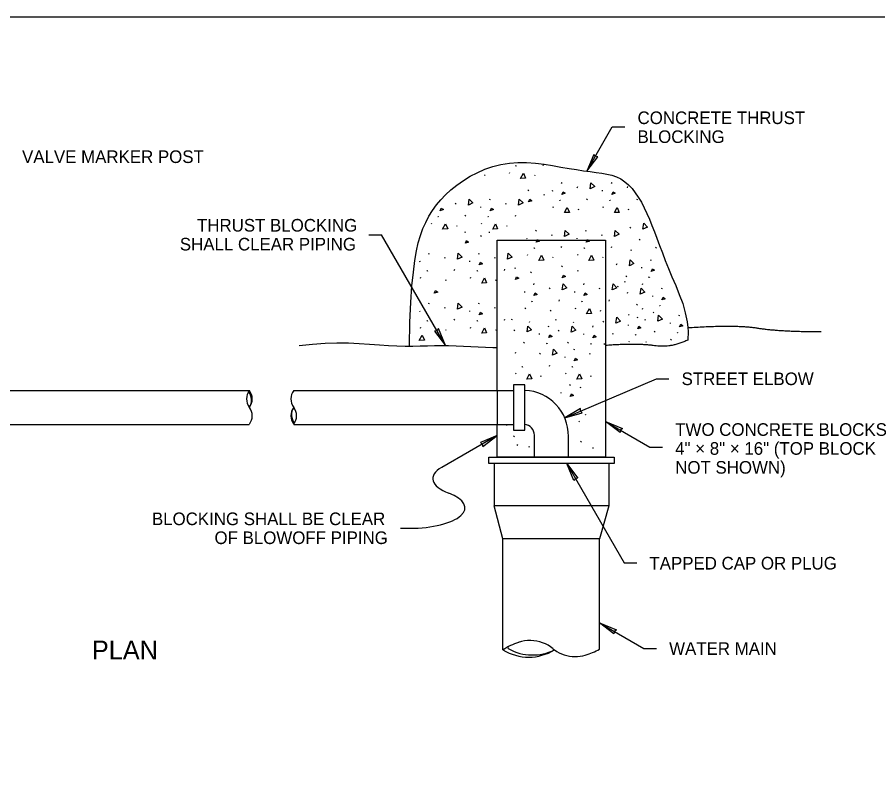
# Model space of a CAD drawing. Extents: x 99862 to 103151, y 99999 to 102075.
# Drawn here: x 100960 to 102052, y 101093 to 102075 of the extents above; entities that cross this region are included whole.
import ezdxf

# ---------------------------------------------------------------- set-up
doc = ezdxf.new("R2010")
doc.units = 0
for name, color, linetype in [('Level 1', 7, 'Continuous'), ('Level 10', 7, 'Continuous'), ('Level 11', 7, 'Continuous'), ('Level 14', 7, 'Continuous'), ('Level 15', 7, 'Continuous'), ('Level 17', 7, 'Continuous'), ('Level 20', 7, 'Continuous'), ('Level 6', 7, 'Continuous')]:
    doc.layers.add(name, color=color, linetype=linetype)

msp = doc.modelspace()

# ---------------------------------------------------------------- linework, layer by layer
at = {"layer": 'Level 1'}
for p, q in [((101592.4, 101887.3), (101593, 101886.5)), ((101593, 101887), (101593.4, 101886.3)), ((101627.5, 101887.3), (101627.9, 101888.6)), ((101584.6, 101877.4), (101585.1, 101878.6)), ((101553.2, 101874.5), (101553.8, 101875.6)), ((101616.7, 101874.5), (101617.1, 101875.6)), ((101650.8, 101864.6), (101651.4, 101865.8)), ((101714.3, 101864.6), (101714.8, 101865.8)), ((101608.6, 101855.2), (101609.1, 101856.5)), ((101639, 101855.9), (101639.2, 101854.8)), ((101670.8, 101859.2), (101671.6, 101860.5)), ((101702.5, 101855.9), (101702.5, 101854.8)), ((101734.5, 101859.2), (101734.9, 101860.5)), ((101559.9, 101843.8), (101560.4, 101845)), ((101628.6, 101849.8), (101629.3, 101851.1)), ((101648.1, 101843.8), (101648.5, 101843.1)), ((101648.5, 101843.6), (101649.1, 101842.9)), ((101682.9, 101843.8), (101683.6, 101845.1)), ((101711.5, 101843.8), (101712, 101843.1)), ((101712, 101843.6), (101712.5, 101842.9)), ((101746.6, 101843.8), (101747, 101845.1)), ((101516.4, 101838.4), (101517.2, 101839.7)), ((101548.1, 101835.1), (101548.1, 101834)), ((101580.1, 101838.4), (101580.5, 101839.7)), ((101640.1, 101834), (101640.7, 101835.2)), ((101672.3, 101831.1), (101672.8, 101832.2)), ((101703.7, 101834), (101704.2, 101835.2)), ((101735.8, 101831.1), (101736.2, 101832.2)), ((101493.7, 101823), (101494.1, 101822.3)), ((101494.1, 101822.7), (101494.7, 101822.1)), ((101528.5, 101823), (101529.2, 101824.3)), ((101557.1, 101823), (101557.6, 101822.3)), ((101557.6, 101822.7), (101558.1, 101822.1)), ((101592.2, 101823), (101592.6, 101824.3)), ((101485.7, 101813.2), (101486.3, 101814.3)), ((101517.8, 101810.2), (101518.4, 101811.4)), ((101549.2, 101813.2), (101549.8, 101814.3)), ((101581.4, 101810.2), (101581.8, 101811.4)), ((101528.4, 101802.5), (101529, 101803.8)), ((101558.8, 101803.2), (101559, 101802.1)), ((101618.2, 101804), (101618.8, 101805.2)), ((101638.3, 101798.6), (101639, 101799.9)), ((101681.8, 101804), (101682.2, 101805.2)), ((101701.9, 101798.6), (101702.4, 101799.9)), ((101737.8, 101807.7), (101738.5, 101809)), ((101548.4, 101797.1), (101549.2, 101798.4)), ((101606.5, 101795.3), (101606.6, 101794.2)), ((101670, 101795.3), (101670, 101794.2)), ((101749.8, 101792.4), (101750.5, 101793.7)), ((101615.5, 101783.2), (101616, 101782.5)), ((101616, 101782.9), (101616.5, 101782.2)), ((101650.4, 101783.2), (101651.1, 101784.5)), ((101678.9, 101783.2), (101679.5, 101782.5)), ((101679.5, 101782.9), (101679.9, 101782.2)), ((101714, 101783.2), (101714.4, 101784.5)), ((101739.2, 101779.6), (101739.7, 101780.7)), ((101770.6, 101782.5), (101771.1, 101783.7)), ((101482.4, 101775), (101483, 101776.3)), ((101502.5, 101769.6), (101503.2, 101770.9)), ((101546, 101775), (101546.4, 101776.3)), ((101566.1, 101769.6), (101566.5, 101770.9)), ((101607.6, 101773.4), (101608.2, 101774.5)), ((101639.7, 101770.4), (101640.3, 101771.6)), ((101671.1, 101773.4), (101671.7, 101774.5)), ((101703.2, 101770.4), (101703.7, 101771.6)), ((101764.2, 101766.9), (101764.6, 101768.2)), ((101470.6, 101766.4), (101470.8, 101765.2)), ((101534.1, 101766.4), (101534.1, 101765.2)), ((101591.9, 101756.7), (101592.4, 101757.9)), ((101651.3, 101758.8), (101651.8, 101760.1)), ((101720.7, 101761.5), (101721.4, 101762.8)), ((101752.4, 101758.3), (101752.4, 101757.1)), ((101471.8, 101744.5), (101472.3, 101745.6)), ((101479.7, 101754.3), (101480.1, 101753.6)), ((101480.1, 101754), (101480.7, 101753.3)), ((101514.6, 101754.3), (101515.3, 101755.6)), ((101535.3, 101744.5), (101535.8, 101745.6)), ((101543.1, 101754.3), (101543.7, 101753.6)), ((101543.7, 101754), (101544.1, 101753.3)), ((101578.2, 101754.3), (101578.6, 101755.6)), ((101611.9, 101751.3), (101612.6, 101752.6)), ((101671.3, 101753.4), (101672, 101754.7)), ((101732.8, 101746.2), (101733.5, 101747.5)), ((101761.3, 101746.2), (101761.9, 101745.4)), ((101761.9, 101745.9), (101762.4, 101745.2)), ((101503.9, 101741.5), (101504.5, 101742.6)), ((101567.4, 101741.5), (101567.8, 101742.6)), ((101615.4, 101736.1), (101616, 101737.4)), ((101679, 101736.1), (101679.4, 101737.4)), ((101722.1, 101733.4), (101722.7, 101734.5)), ((101731.2, 101739.4), (101731.6, 101740.5)), ((101753.5, 101736.3), (101754.1, 101737.5)), ((101603.6, 101727.5), (101603.8, 101726.3)), ((101635.5, 101730.7), (101636.2, 101732)), ((101667.1, 101727.5), (101667.1, 101726.3)), ((101699.1, 101730.7), (101699.5, 101732)), ((101734.4, 101725.4), (101735.1, 101726.7)), ((101777.9, 101730.8), (101778.3, 101732.1)), ((101482.4, 101711.7), (101483, 101713)), ((101546, 101711.7), (101546.4, 101713)), ((101612.7, 101715.4), (101613.1, 101714.7)), ((101613.1, 101715.1), (101613.7, 101714.4)), ((101647.6, 101715.4), (101648.3, 101716.7)), ((101676.1, 101715.4), (101676.7, 101714.7)), ((101676.7, 101715.1), (101677.1, 101714.4)), ((101711.2, 101715.4), (101711.6, 101716.7)), ((101766.1, 101722.1), (101766.1, 101721)), ((101470.6, 101703), (101470.8, 101701.9)), ((101502.5, 101706.3), (101503.2, 101707.6)), ((101534.1, 101703), (101534.1, 101701.9)), ((101566.1, 101706.3), (101566.5, 101707.6)), ((101604.8, 101705.6), (101605.3, 101706.7)), ((101636.9, 101702.6), (101637.5, 101703.7)), ((101668.3, 101705.6), (101668.9, 101706.7)), ((101700.4, 101702.6), (101700.8, 101703.7)), ((101746.5, 101710), (101747.2, 101711.3)), ((101753.5, 101705.1), (101753.9, 101706.3)), ((101767.2, 101700.2), (101767.8, 101701.4)), ((101775, 101710), (101775.6, 101709.3)), ((101775.6, 101709.8), (101776.1, 101709.1)), ((101479.7, 101690.9), (101480.1, 101690.2)), ((101480.1, 101690.7), (101480.7, 101690)), ((101514.6, 101690.9), (101515.3, 101692.2)), ((101543.1, 101690.9), (101543.7, 101690.2)), ((101543.7, 101690.7), (101544.1, 101690)), ((101578.2, 101690.9), (101578.6, 101692.2)), ((101587.6, 101691.4), (101588, 101692.6)), ((101643.7, 101691.1), (101644.1, 101692.2)), ((101735.8, 101697.3), (101736.4, 101698.4)), ((101747.1, 101694), (101747.5, 101695.2)), ((101756.7, 101691.1), (101757.4, 101692.4)), ((101800.2, 101696.5), (101800.6, 101697.8)), ((101471.8, 101681.1), (101472.3, 101682.3)), ((101503.9, 101678.2), (101504.5, 101679.3)), ((101535.3, 101681.1), (101535.8, 101682.3)), ((101567.4, 101678.2), (101567.8, 101679.3)), ((101609.9, 101688.4), (101610.5, 101689.5)), ((101634.3, 101682.8), (101634.7, 101684.1)), ((101665.9, 101688), (101666.5, 101689.1)), ((101690.3, 101682.4), (101690.8, 101683.7)), ((101703.6, 101688.6), (101704.3, 101689.9)), ((101735.3, 101685.3), (101735.3, 101684.2)), ((101788.4, 101687.8), (101788.4, 101686.7)), ((101590.8, 101677.4), (101591.5, 101678.7)), ((101622.5, 101674.1), (101622.5, 101673)), ((101646.8, 101677), (101647.6, 101678.3)), ((101678.5, 101673.8), (101678.5, 101672.7)), ((101715.7, 101673.2), (101716.4, 101674.5)), ((101744.3, 101673.2), (101744.8, 101672.5)), ((101744.8, 101672.9), (101745.3, 101672.2)), ((101768.8, 101675.8), (101769.5, 101677)), ((101797.3, 101675.8), (101797.9, 101675)), ((101797.9, 101675.5), (101798.4, 101674.8)), ((101602.9, 101662), (101603.6, 101663.3)), ((101631.4, 101662), (101632, 101661.3)), ((101632, 101661.8), (101632.4, 101661.1)), ((101658.9, 101661.7), (101659.6, 101663)), ((101687.5, 101661.7), (101688.1, 101661)), ((101688.1, 101661.4), (101688.5, 101660.7)), ((101705, 101660.4), (101705.6, 101661.6)), ((101736.4, 101663.4), (101737, 101664.5)), ((101758.1, 101663), (101758.7, 101664.1)), ((101789.5, 101665.9), (101790.1, 101667.1)), ((101592.2, 101649.3), (101592.8, 101650.4)), ((101623.2, 101647.9), (101623.9, 101649.2)), ((101666.6, 101653.3), (101667.1, 101654.6)), ((101686.8, 101647.9), (101687.2, 101649.2)), ((101654.8, 101644.7), (101654.8, 101643.5)), ((101600.4, 101632.6), (101600.8, 101631.9)), ((101600.8, 101632.3), (101601.4, 101631.6)), ((101635.3, 101632.6), (101635.9, 101633.9)), ((101663.8, 101632.6), (101664.4, 101631.9)), ((101664.4, 101632.3), (101664.8, 101631.6)), ((101592.5, 101622.8), (101593, 101623.9)), ((101624.6, 101619.8), (101625.1, 101620.9)), ((101656, 101622.8), (101656.5, 101623.9)), ((101688.1, 101619.8), (101688.5, 101620.9)), ((101661.5, 101608.1), (101662, 101609.4)), ((101674.7, 101605.1), (101675.3, 101606.4)), ((101649.7, 101599.5), (101649.8, 101598.3)), ((101680.8, 101571.8), (101681.2, 101571)), ((101681.2, 101571.5), (101681.7, 101570.8)), ((101672.8, 101561.9), (101673.4, 101563.1)), ((101581.4, 101557.6), (101581.4, 101558.9)), ((101590.3, 101543), (101591, 101544.3)), ((101675.4, 101536.4), (101675.9, 101537.6)), ((101594.6, 101531.9), (101595.2, 101533.2)), ((101609.5, 101529.8), (101610.2, 101531.1)), ((101690.3, 101529.6), (101690.4, 101528.4))]:
    msp.add_line(p, q, dxfattribs=at)
msp.add_lwpolyline([(99862, 99999.5), (103151, 99999.5), (103151, 102075.5), (99862, 102075.5)], close=True, dxfattribs=at)
for points in [[(101598.8, 101870.9), (101602.3, 101877.6), (101605, 101871.3), (101598.9, 101870.9)], [(101687, 101857.9), (101688.1, 101865.4), (101692.9, 101860.6), (101687.2, 101857.9)], [(101651.1, 101850.7), (101652.7, 101854.1), (101655.3, 101852.1), (101651.1, 101850.7)], [(101714.6, 101850.7), (101716.2, 101854.1), (101718.7, 101852.1), (101714.6, 101850.7)], [(101532.6, 101837.1), (101533.6, 101844.6), (101538.4, 101839.8), (101532.8, 101837.1)], [(101596.2, 101837.1), (101597.1, 101844.6), (101602, 101839.8), (101596.3, 101837.1)], [(101608.9, 101841.3), (101610.4, 101844.7), (101613.1, 101842.7), (101608.9, 101841.3)], [(101496.7, 101829.9), (101498.2, 101833.3), (101500.9, 101831.3), (101496.7, 101829.9)], [(101560.2, 101829.9), (101561.7, 101833.3), (101564.3, 101831.3), (101560.2, 101829.9)], [(101654.4, 101827.5), (101657.9, 101834.2), (101660.8, 101827.9), (101654.5, 101827.5)], [(101717.9, 101827.5), (101721.4, 101834.2), (101724.1, 101827.9), (101718, 101827.5)], [(101499.9, 101806.7), (101503.5, 101813.4), (101506.4, 101807.1), (101500.1, 101806.7)], [(101563.4, 101806.7), (101567, 101813.4), (101569.7, 101807.1), (101563.6, 101806.7)], [(101754, 101806.4), (101755, 101814), (101759.8, 101809.1), (101754.1, 101806.4)], [(101654.5, 101797.3), (101655.5, 101804.8), (101660.3, 101800), (101654.6, 101797.3)], [(101718, 101797.3), (101719, 101804.8), (101723.8, 101800), (101718.1, 101797.3)], [(101528.7, 101788.6), (101530.3, 101792), (101532.9, 101790), (101528.7, 101788.6)], [(101618.5, 101790), (101620.1, 101793.4), (101622.8, 101791.5), (101618.5, 101790)], [(101682.1, 101790), (101683.6, 101793.4), (101686.2, 101791.5), (101682.1, 101790)], [(101518.7, 101768.3), (101519.7, 101775.9), (101524.5, 101771.1), (101518.8, 101768.3)], [(101582.2, 101768.3), (101583.2, 101775.9), (101588, 101771.1), (101582.3, 101768.3)], [(101621.8, 101766.9), (101625.4, 101773.5), (101628.2, 101767.3), (101622, 101766.9)], [(101685.3, 101766.9), (101688.9, 101773.5), (101691.6, 101767.3), (101685.5, 101766.9)], [(101736.9, 101760.2), (101737.9, 101767.8), (101742.7, 101762.9), (101737, 101760.2)], [(101546.2, 101761.1), (101547.8, 101764.5), (101550.4, 101762.5), (101546.2, 101761.1)], [(101764.5, 101753), (101766, 101756.4), (101768.6, 101754.4), (101764.5, 101753)], [(101592.2, 101742.8), (101593.7, 101746.2), (101596.4, 101744.2), (101592.2, 101742.8)], [(101651.6, 101744.9), (101653.1, 101748.3), (101655.8, 101746.3), (101651.6, 101744.9)], [(101549.5, 101738), (101553.1, 101744.6), (101555.7, 101738.4), (101549.6, 101738)], [(101651.7, 101729.4), (101652.7, 101737), (101657.5, 101732.1), (101651.8, 101729.4)], [(101715.2, 101729.4), (101716.2, 101737), (101721, 101732.1), (101715.3, 101729.4)], [(101489.3, 101725.2), (101490.9, 101728.6), (101493.6, 101726.6), (101489.3, 101725.2)], [(101615.7, 101722.2), (101617.3, 101725.6), (101620, 101723.6), (101615.7, 101722.2)], [(101679.2, 101722.2), (101680.8, 101725.6), (101683.4, 101723.6), (101679.2, 101722.2)], [(101750.6, 101724.1), (101751.6, 101731.6), (101756.4, 101726.8), (101750.7, 101724.1)], [(101518.7, 101705), (101519.7, 101712.5), (101524.5, 101707.7), (101518.8, 101705)], [(101778.2, 101716.9), (101779.7, 101720.3), (101782.3, 101718.3), (101778.2, 101716.9)], [(101546.2, 101697.8), (101547.8, 101701.2), (101550.4, 101699.2), (101546.2, 101697.8)], [(101682.5, 101699.1), (101686.1, 101705.7), (101688.7, 101699.5), (101682.7, 101699.1)], [(101719.8, 101687.3), (101720.8, 101694.8), (101725.6, 101690), (101719.9, 101687.3)], [(101772.9, 101689.8), (101773.9, 101697.4), (101778.7, 101692.5), (101773, 101689.8)], [(101549.5, 101674.6), (101553.1, 101681.3), (101555.7, 101675), (101549.6, 101674.6)], [(101607, 101676.1), (101608, 101683.6), (101612.8, 101678.8), (101607.1, 101676.1)], [(101663, 101675.8), (101664.1, 101683.3), (101668.9, 101678.5), (101663.2, 101675.8)], [(101747.4, 101680), (101748.9, 101683.5), (101751.5, 101681.5), (101747.4, 101680)], [(101800.5, 101682.6), (101802, 101686), (101804.6, 101684), (101800.5, 101682.6)], [(101470.2, 101665.4), (101473.8, 101672), (101476.7, 101665.8), (101470.4, 101665.4)], [(101634.6, 101668.9), (101636.1, 101672.3), (101638.7, 101670.3), (101634.6, 101668.9)], [(101690.6, 101668.5), (101692.2, 101671.9), (101694.7, 101669.9), (101690.6, 101668.5)], [(101639.4, 101646.6), (101640.4, 101654.2), (101645.2, 101649.4), (101639.5, 101646.6)], [(101666.9, 101639.4), (101668.5, 101642.8), (101671.1, 101640.8), (101666.9, 101639.4)], [(101606.7, 101616.3), (101610.2, 101622.9), (101613.1, 101616.7), (101606.8, 101616.3)], [(101670.2, 101616.3), (101673.7, 101622.9), (101676.4, 101616.7), (101670.3, 101616.3)], [(101661.8, 101594.2), (101663.3, 101597.6), (101666, 101595.6), (101661.8, 101594.2)]]:
    msp.add_lwpolyline(points, dxfattribs=at)
at = {"layer": 'Level 10'}
msp.add_line((101810.6, 101670.5), (101810.6, 101670.5), dxfattribs=at)
at = {"layer": 'Level 11'}
msp.add_arc((101584.5, 101275.5), 1.7, 130.6423, 246.1953, dxfattribs=at)
at = {"layer": 'Level 14'}
msp.add_line((101446.6, 101427), (101458.6, 101427), dxfattribs=at)
for centre, start_param, end_param in [((101557, 101490), 5.707161, 7.068624), ((101458.6, 101453.1), 1.570796, 3.926959)]:
    msp.add_ellipse(centre, major_axis=(-69.6, 0), ratio=0.375, start_param=start_param, end_param=end_param, dxfattribs=at)
at = {"layer": 'Level 15'}
for p, q in [((101682.7, 101880.2), (101715.2, 101936.5)), ((101715.2, 101936.5), (101731.2, 101936.5)), ((101406.3, 101799.5), (101422.3, 101799.5)), ((101503.4, 101659), (101422.3, 101799.5)), ((101654.9, 101567.1), (101771.1, 101616.7)), ((101771.1, 101616.7), (101787.1, 101616.7)), ((101706.7, 101562.5), (101763, 101530)), ((101569, 101544.8), (101498.7, 101504.2)), ((101763, 101530), (101779, 101530)), ((101657.6, 101509.1), (101730.3, 101383.1)), ((101730.3, 101383.1), (101746.3, 101383.1)), ((101699, 101306.9), (101755.3, 101274.4)), ((101755.3, 101274.4), (101771.3, 101274.4))]:
    msp.add_line(p, q, dxfattribs=at)
for points in [[(101682.7, 101880.2), (101696.7, 101898.4), (101693.6, 101899), (101691.6, 101901.4)], [(101503.4, 101659), (101494.6, 101680.3), (101492.5, 101677.9), (101489.4, 101677.3)], [(101654.9, 101567.1), (101677.1, 101573.3), (101675, 101575.6), (101674.8, 101578.8)], [(101706.7, 101562.5), (101728, 101553.7), (101725.6, 101551.6), (101725, 101548.5)], [(101569, 101544.8), (101547.8, 101536), (101550.2, 101533.9), (101550.8, 101530.8)], [(101657.6, 101509.1), (101671.6, 101490.8), (101668.5, 101490.2), (101666.5, 101487.8)], [(101699, 101306.9), (101720.3, 101298.1), (101717.9, 101296.1), (101717.3, 101292.9)]]:
    msp.add_lwpolyline(points, close=True, dxfattribs=at)
at = {"layer": 'Level 17'}
msp.add_line((101569, 101602), (101569, 101558.9), dxfattribs=at)
for points in [[(101457.7, 101658.3), (101458.4, 101688.4), (101459.5, 101713.5), (101460.9, 101734.7), (101462.7, 101751.9), (101464.5, 101766.6), (101466.6, 101778.9), (101468.7, 101789.2), (101471.7, 101798.6), (101474.8, 101807.2), (101478.4, 101815), (101482.4, 101822.9), (101487.1, 101830.1), (101492.1, 101837.3), (101497.4, 101843.8), (101503.5, 101850.2), (101510.4, 101856.3), (101517.9, 101862.4), (101526.2, 101868.2), (101534.8, 101873.6), (101543.7, 101878.2), (101553.4, 101882.5), (101563.5, 101886.1), (101573.9, 101888.6), (101584.6, 101890.4), (101595.4, 101891.1), (101606.5, 101891.1), (101617.6, 101890.4), (101628.8, 101889), (101639.5, 101887.2), (101649.9, 101885.4), (101660.4, 101883.6), (101669.7, 101882.1), (101678.6, 101880.7), (101686.9, 101879.6), (101694.7, 101878.5), (101701.9, 101877.5), (101708.4, 101876.4), (101714.5, 101874.9), (101720.6, 101872.8), (101726, 101870.3), (101731, 101866.7), (101735.6, 101862.8), (101740.3, 101858.1), (101744.3, 101852.7), (101748.2, 101847), (101752.2, 101840.6), (101755.8, 101833.7), (101759, 101826.5), (101762.2, 101819.4), (101765.4, 101811.4), (101768.7, 101803.2), (101771.5, 101795), (101775.1, 101786), (101778.7, 101776.7), (101782.3, 101767), (101786.6, 101756.6), (101790.9, 101746.2), (101795.9, 101735.1), (101800.2, 101723.6), (101804.5, 101712.1), (101807.8, 101700.3), (101810.3, 101688.8), (101811, 101681.6)], [(101569, 101602), (101569, 101792.7), (101706.7, 101792.7), (101706.7, 101517.3), (101569, 101517.3), (101569, 101558.9)], [(101811, 101681.6), (101811.3, 101676.9), (101811, 101665.8)], [(101317.7, 101659), (101334.6, 101660.8), (101350.8, 101661.9), (101365.8, 101662.3), (101380.5, 101662.3), (101394.1, 101661.5), (101407.1, 101660.8), (101419.6, 101659.7), (101431.1, 101659), (101441.8, 101658.7), (101452.3, 101658.3), (101457.7, 101658.3)], [(101457.7, 101658.3), (101462, 101658.3), (101471.2, 101658.7), (101480.6, 101658.7), (101489.6, 101659), (101498.5, 101659), (101507.5, 101659), (101516.9, 101658.7), (101526.2, 101658.3), (101535.5, 101657.6), (101544.8, 101657.2), (101554.2, 101656.9), (101563.5, 101656.5), (101569, 101656.5)]]:
    msp.add_lwpolyline(points, dxfattribs=at)
for points in [[(101811, 101681.6), (101872, 101685.6), (101926.8, 101676.6), (101980.3, 101676.6)], [(101811, 101665.8), (101788.8, 101655.4), (101747.9, 101661.9), (101706.7, 101659)]]:
    msp.add_open_spline(points, degree=2, dxfattribs=at)
at = {"layer": 'Level 6'}
for p, q in [((101604, 101609.2), (101589.7, 101609.2)), ((101589.7, 101609.2), (101589.7, 101551.7)), ((101604, 101551.7), (101604, 101609.2)), ((100852.4, 101602), (101254.6, 101602)), ((101310.9, 101602), (101589.7, 101602)), ((100852.4, 101558.9), (101254.2, 101558.9)), ((101310.9, 101558.9), (101589.7, 101558.9)), ((101589.7, 101551.7), (101604, 101551.7)), ((101616.5, 101517.3), (101616.5, 101545.2)), ((101659.6, 101517.3), (101659.6, 101543.6)), ((101558.4, 101509.1), (101558.4, 101517.3)), ((101558.4, 101517.3), (101717.4, 101517.3)), ((101717.4, 101517.3), (101717.4, 101509.1)), ((101717.4, 101509.1), (101558.4, 101509.1)), ((101565.3, 101509.1), (101565.3, 101455.6)), ((101710.6, 101509.1), (101710.6, 101455.6)), ((101710.6, 101455.6), (101565.3, 101455.6)), ((101576.4, 101413.7), (101565.3, 101455.6)), ((101710.6, 101455.6), (101699, 101413.7)), ((101699, 101413.7), (101576.4, 101413.7)), ((101576.4, 101272.6), (101576.4, 101413.7)), ((101699, 101273.8), (101699, 101413.7))]:
    msp.add_line(p, q, dxfattribs=at)
for centre, radius, start, end in [((101268.5, 101591.2), 17.5, 142.1725, 217.8275), ((101240.2, 101589.7), 17.1, 327.2975, 38.8533), ((101240.8, 101591.2), 17.5, 322.1725, 37.8275), ((101324.8, 101591.2), 17.5, 142.1725, 217.8275), ((101602.1, 101544.6), 57.4, 359.0671, 87.9807), ((101240.8, 101569.7), 17.5, 322.1725, 37.8275), ((101324.8, 101569.7), 17.5, 142.1725, 217.8275), ((101325.2, 101571), 17.1, 146.7149, 218.8002), ((101297.1, 101569.7), 17.5, 322.1725, 37.8275), ((101602.1, 101544.6), 14.4, 2.5137, 82.6184), ((101609.1, 101326), 62.5, 238.502, 238.502), ((101623.1, 101201.5), 85.1, 108.5999, 123.1818), ((101610.6, 101238.6), 46, 88.7194, 108.5999), ((101610.6, 101237.8), 46.8, 51.1087, 88.7194), ((101609.1, 101326), 62.5, 238.502, 301.5471), ((101613.9, 101328.3), 62.1, 240.9854, 296.6601), ((101668, 101309), 44.8, 231.1087, 234.156), ((101668, 101309), 44.8, 234.156, 269.5848), ((101668, 101311.7), 47.4, 269.5848, 285.7783), ((101657.7, 101348.4), 85.5, 285.7783, 298.99)]:
    msp.add_arc(centre, radius, start, end, dxfattribs=at)

# ---------------------------------------------------------------- texts
at = {"layer": 'Level 20'}
for s, height, p in [('CONCRETE THRUST', 16, (101747.2, 101939.9)), ('BLOCKING', 16, (101747.2, 101915.9)), ('VALVE MARKER POST', 16, (100966.2, 101890.5)), ('THRUST BLOCKING', 16, (101188.2, 101803.5)), ('SHALL CLEAR PIPING', 16, (101166.4, 101779.5)), ('STREET ELBOW', 16, (101803.1, 101608.7)), ('TWO CONCRETE BLOCKS', 16, (101795, 101544.3)), ('4" × 8" × 16" (TOP BLOCK', 16, (101795, 101520.3)), ('NOT SHOWN)', 16, (101795, 101496.3)), ('BLOCKING SHALL BE CLEAR', 16, (101131, 101431)), ('OF BLOWOFF PIPING', 16, (101210.4, 101407)), ('TAPPED CAP OR PLUG', 16, (101762.3, 101374.7)), ('PLAN', 24, (101054.8, 101260.5)), ('WATER MAIN', 16, (101787.3, 101266.4))]:
    msp.add_text(s, height=height, dxfattribs=at).set_placement(p)

doc.saveas('drawing.dxf')
